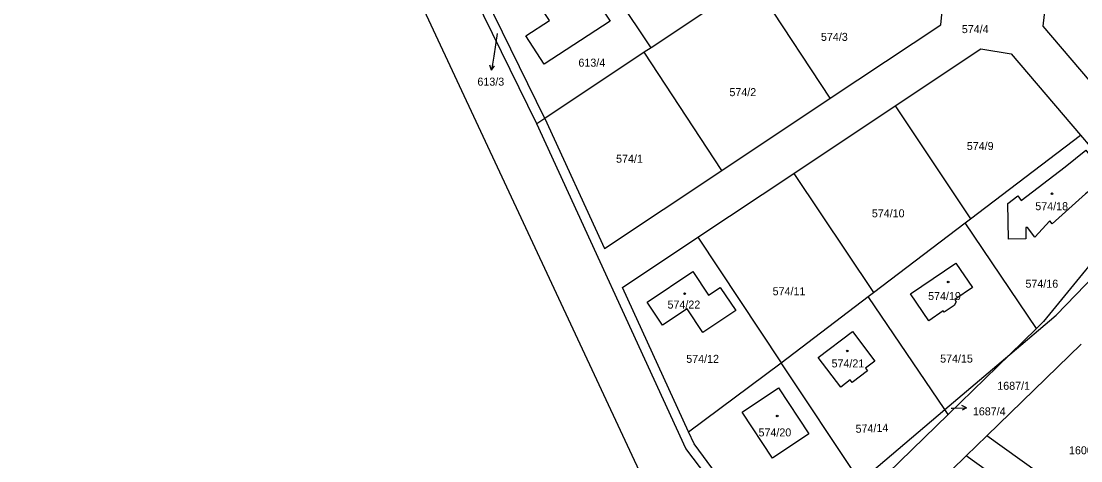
# Model space of a CAD drawing. Extents: x -724107 to -720612, y -1045267 to -1038441.
# Drawn here: x -723206 to -722981, y -1043179.2 to -1043085.8 of the extents above; entities that cross this region are included whole.
import ezdxf

# ---------------------------------------------------------------- set-up
doc = ezdxf.new("R2010")
doc.units = 0
for name, color, linetype in [('Hranice kat_území', 7, 'Continuous'), ('Hranice parcel', 7, 'Continuous'), ('Parcelní čísla', 7, 'Continuous'), ('Pop  PČ popisy', 7, 'Continuous'), ('Značky budov', 7, 'Continuous')]:
    doc.layers.add(name, color=color, linetype=linetype)

msp = doc.modelspace()

# ---------------------------------------------------------------- linework, layer by layer
at = {"layer": 'Hranice kat_území'}
msp.add_lwpolyline([(-723212.07, -1042985.4), (-723153.02, -1043045.8), (-723124.07, -1043075.78), (-723072.76, -1043185.61)], dxfattribs=at)
at = {"layer": 'Hranice parcel'}
for p, q in [((-723072.24, -1043091.5), (-723091.93, -1043061.97)), ((-723094.79, -1043106.51), (-723110.63, -1043074.28)), ((-723096.47, -1043107.63), (-723112.31, -1043075.39)), ((-723034.19, -1043102.21), (-723050.65, -1043077.13)), ((-723051.58, -1043077.75), (-723072.24, -1043091.5)), ((-723073.67, -1043092.45), (-723094.79, -1043106.51)), ((-723072.24, -1043091.5), (-723073.67, -1043092.45)), ((-723057.21, -1043117.54), (-723073.67, -1043092.45)), ((-723057.21, -1043117.54), (-723034.19, -1043102.21)), ((-723041.92, -1043118.17), (-723020.41, -1043103.85)), ((-723020.41, -1043103.85), (-723004.41, -1043127.85)), ((-723094.79, -1043106.51), (-723096.47, -1043107.63)), ((-723004.41, -1043127.85), (-722981.01, -1043110.06)), ((-723062.33, -1043131.76), (-723041.92, -1043118.17)), ((-723041.92, -1043118.17), (-723025.02, -1043143.51)), ((-723025.02, -1043143.51), (-723005.51, -1043128.68)), ((-723005.51, -1043128.68), (-723004.41, -1043127.85)), ((-722990.35, -1043151.12), (-723005.51, -1043128.68)), ((-723062.33, -1043131.76), (-723044.6, -1043158.4)), ((-723044.6, -1043158.4), (-723026.09, -1043144.32)), ((-723026.09, -1043144.32), (-723025.02, -1043143.51)), ((-723009.84, -1043168.37), (-723026.09, -1043144.32)), ((-722990.35, -1043151.12), (-722996.05, -1043156.65)), ((-722980.9, -1043154.48), (-723000.95, -1043173.97)), ((-723064.27, -1043173.06), (-723044.6, -1043158.4)), ((-723028.1, -1043183.18), (-723044.6, -1043158.4)), ((-723009.84, -1043168.37), (-722996.05, -1043156.65)), ((-722996.05, -1043156.65), (-723009.15, -1043169.39)), ((-723009.15, -1043169.39), (-723026.23, -1043185.99)), ((-723009.15, -1043169.39), (-723009.84, -1043168.37)), ((-723000.95, -1043173.97), (-723005.32, -1043178.22)), ((-722974.63, -1043192.72), (-723000.95, -1043173.97)), ((-723005.32, -1043178.22), (-723034.68, -1043206.75)), ((-722989.59, -1043189.43), (-723005.32, -1043178.22))]:
    msp.add_line(p, q, dxfattribs=at)
for points in [[(-723034.19, -1043102.21), (-723010.72, -1043086.59), (-723010.24, -1043082.31), (-723030.75, -1043063.88)], [(-723098.86, -1043088.97), (-723093.84, -1043085.7), (-723097.1, -1043080.73), (-723102.13, -1043084), (-723106.07, -1043077.97), (-723092.09, -1043068.81), (-723080.95, -1043085.85), (-723094.93, -1043094.98), (-723098.86, -1043088.97)], [(-722945.06, -1043096.05), (-722960.35, -1043114.76), (-722965.13, -1043114.8), (-722988.93, -1043086.93), (-722988.42, -1043082.56), (-722975.28, -1043073.81)], [(-723020.41, -1043103.85), (-723002.18, -1043091.72), (-722995.77, -1043092.78), (-722981.01, -1043110.06)], [(-722996.05, -1043156.65), (-722986.19, -1043148.28), (-722969.54, -1043131.08), (-722942.44, -1043095.55)], [(-723094.79, -1043106.51), (-723082.13, -1043134.12), (-723057.21, -1043117.54)], [(-723050.15, -1043196.04), (-723064.83, -1043176.64), (-723096.47, -1043107.63)], [(-722981.01, -1043110.06), (-722970.75, -1043122.08), (-722970.65, -1043127.38), (-722988.85, -1043149.66), (-722990.35, -1043151.12)], [(-722994.34, -1043122.96), (-722993.61, -1043123.92), (-722984.28, -1043116.81), (-722979.9, -1043113.28), (-722975.44, -1043119.21), (-722979.94, -1043122.53), (-722987.04, -1043128.9), (-722987.5, -1043128.26), (-722990.74, -1043131.74), (-722992.3, -1043129.69), (-722992.66, -1043129.65), (-722992.61, -1043132.11), (-722996.32, -1043132.19), (-722996.45, -1043124.58), (-722994.34, -1043122.96)], [(-723064.27, -1043173.06), (-723078.33, -1043142.41), (-723062.33, -1043131.76)], [(-723010.01, -1043147.66), (-723010.18, -1043147.41), (-723013.27, -1043149.49), (-723017.15, -1043143.75), (-723007.47, -1043137.24), (-723003.98, -1043142.44), (-723007.68, -1043144.96), (-723007.41, -1043145.46), (-723007.87, -1043146.22), (-723010.01, -1043147.66)], [(-723073.06, -1043145.52), (-723063.35, -1043139.06), (-723060.04, -1043144.04), (-723057.53, -1043142.4), (-723054.22, -1043147.31), (-723061.27, -1043151.97), (-723064.58, -1043146.97), (-723069.79, -1043150.43), (-723073.06, -1043145.52)], [(-723026.69, -1043159.56), (-723026.24, -1043160.16), (-723029.51, -1043162.64), (-723029.97, -1043162.05), (-723031.95, -1043163.58), (-723036.71, -1043157.32), (-723029.44, -1043151.79), (-723024.68, -1043158.05), (-723026.69, -1043159.56)], [(-723052.92, -1043168.91), (-723045.18, -1043163.77), (-723038.73, -1043173.49), (-723046.46, -1043178.71), (-723052.92, -1043168.91)], [(-723028.1, -1043183.18), (-723025.43, -1043181.62), (-723009.84, -1043168.37)], [(-723048.32, -1043194.97), (-723049.83, -1043193.62), (-723063.1, -1043175.61), (-723064.27, -1043173.06)]]:
    msp.add_lwpolyline(points, dxfattribs=at)
at = {"layer": 'Pop  PČ popisy'}
for p, q in [((-723104.91, -1043088.46), (-723105.65, -1043093.28)), ((-723105.65, -1043093.28), (-723106.12, -1043096.24)), ((-723106.12, -1043096.24), (-723106.46, -1043095.18)), ((-723106.12, -1043096.24), (-723105.47, -1043095.33)), ((-723005.2, -1043168), (-723006.21, -1043167.51)), ((-723008.52, -1043168.06), (-723008.2, -1043168.05)), ((-723008.2, -1043168.05), (-723005.2, -1043168)), ((-723005.2, -1043168), (-723006.19, -1043168.52))]:
    msp.add_line(p, q, dxfattribs=at)
at = {"layer": 'Značky budov'}
for centre in [(-722987.07, -1043122.52), (-723009.13, -1043141.24), (-723065.11, -1043143.74), (-723030.56, -1043155.91), (-723045.44, -1043169.72)]:
    msp.add_circle(centre, 0.175, dxfattribs=at)

# ---------------------------------------------------------------- texts
at = {"layer": 'Parcelní čísla'}
for s, p in [('574/3', (-723036.15, -1043090.03)), ('574/4', (-723006.23, -1043088.38)), ('613/4', (-723087.66, -1043095.51)), ('613/3', (-723109.12, -1043099.54)), ('574/2', (-723055.59, -1043101.77)), ('574/9', (-723005.17, -1043113.21)), ('574/1', (-723079.67, -1043115.92)), ('574/18', (-722990.62, -1043126)), ('574/10', (-723025.34, -1043127.51)), ('574/11', (-723046.41, -1043144.07)), ('574/16', (-722992.71, -1043142.47)), ('574/19', (-723013.39, -1043145.09)), ('574/22', (-723068.74, -1043146.9)), ('574/12', (-723064.76, -1043158.43)), ('574/21', (-723033.9, -1043159.4)), ('574/15', (-723010.83, -1043158.38)), ('1687/1', (-722998.7, -1043164.16)), ('1687/4', (-723003.88, -1043169.59)), ('574/20', (-723049.41, -1043174.06)), ('1600/6', (-722983.46, -1043177.86))]:
    msp.add_text(s, height=1.7, dxfattribs=at).set_placement(p)
msp.add_text('574/14', height=1.7, rotation=2, dxfattribs=at).set_placement((-723028.77, -1043173.3))

doc.saveas('drawing.dxf')
